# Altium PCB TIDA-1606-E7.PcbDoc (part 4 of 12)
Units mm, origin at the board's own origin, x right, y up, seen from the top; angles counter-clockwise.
Board outline 270 x 345 mm, 4 copper layers (Top Layer, Signal Layer 1, Signal Layer 2, Bottom Layer), stack 2.326 mm thick; 1282 components, 576 nets, 3628 pads, 4132 vias.
Unrouted connection lines stored in the file: 1719.
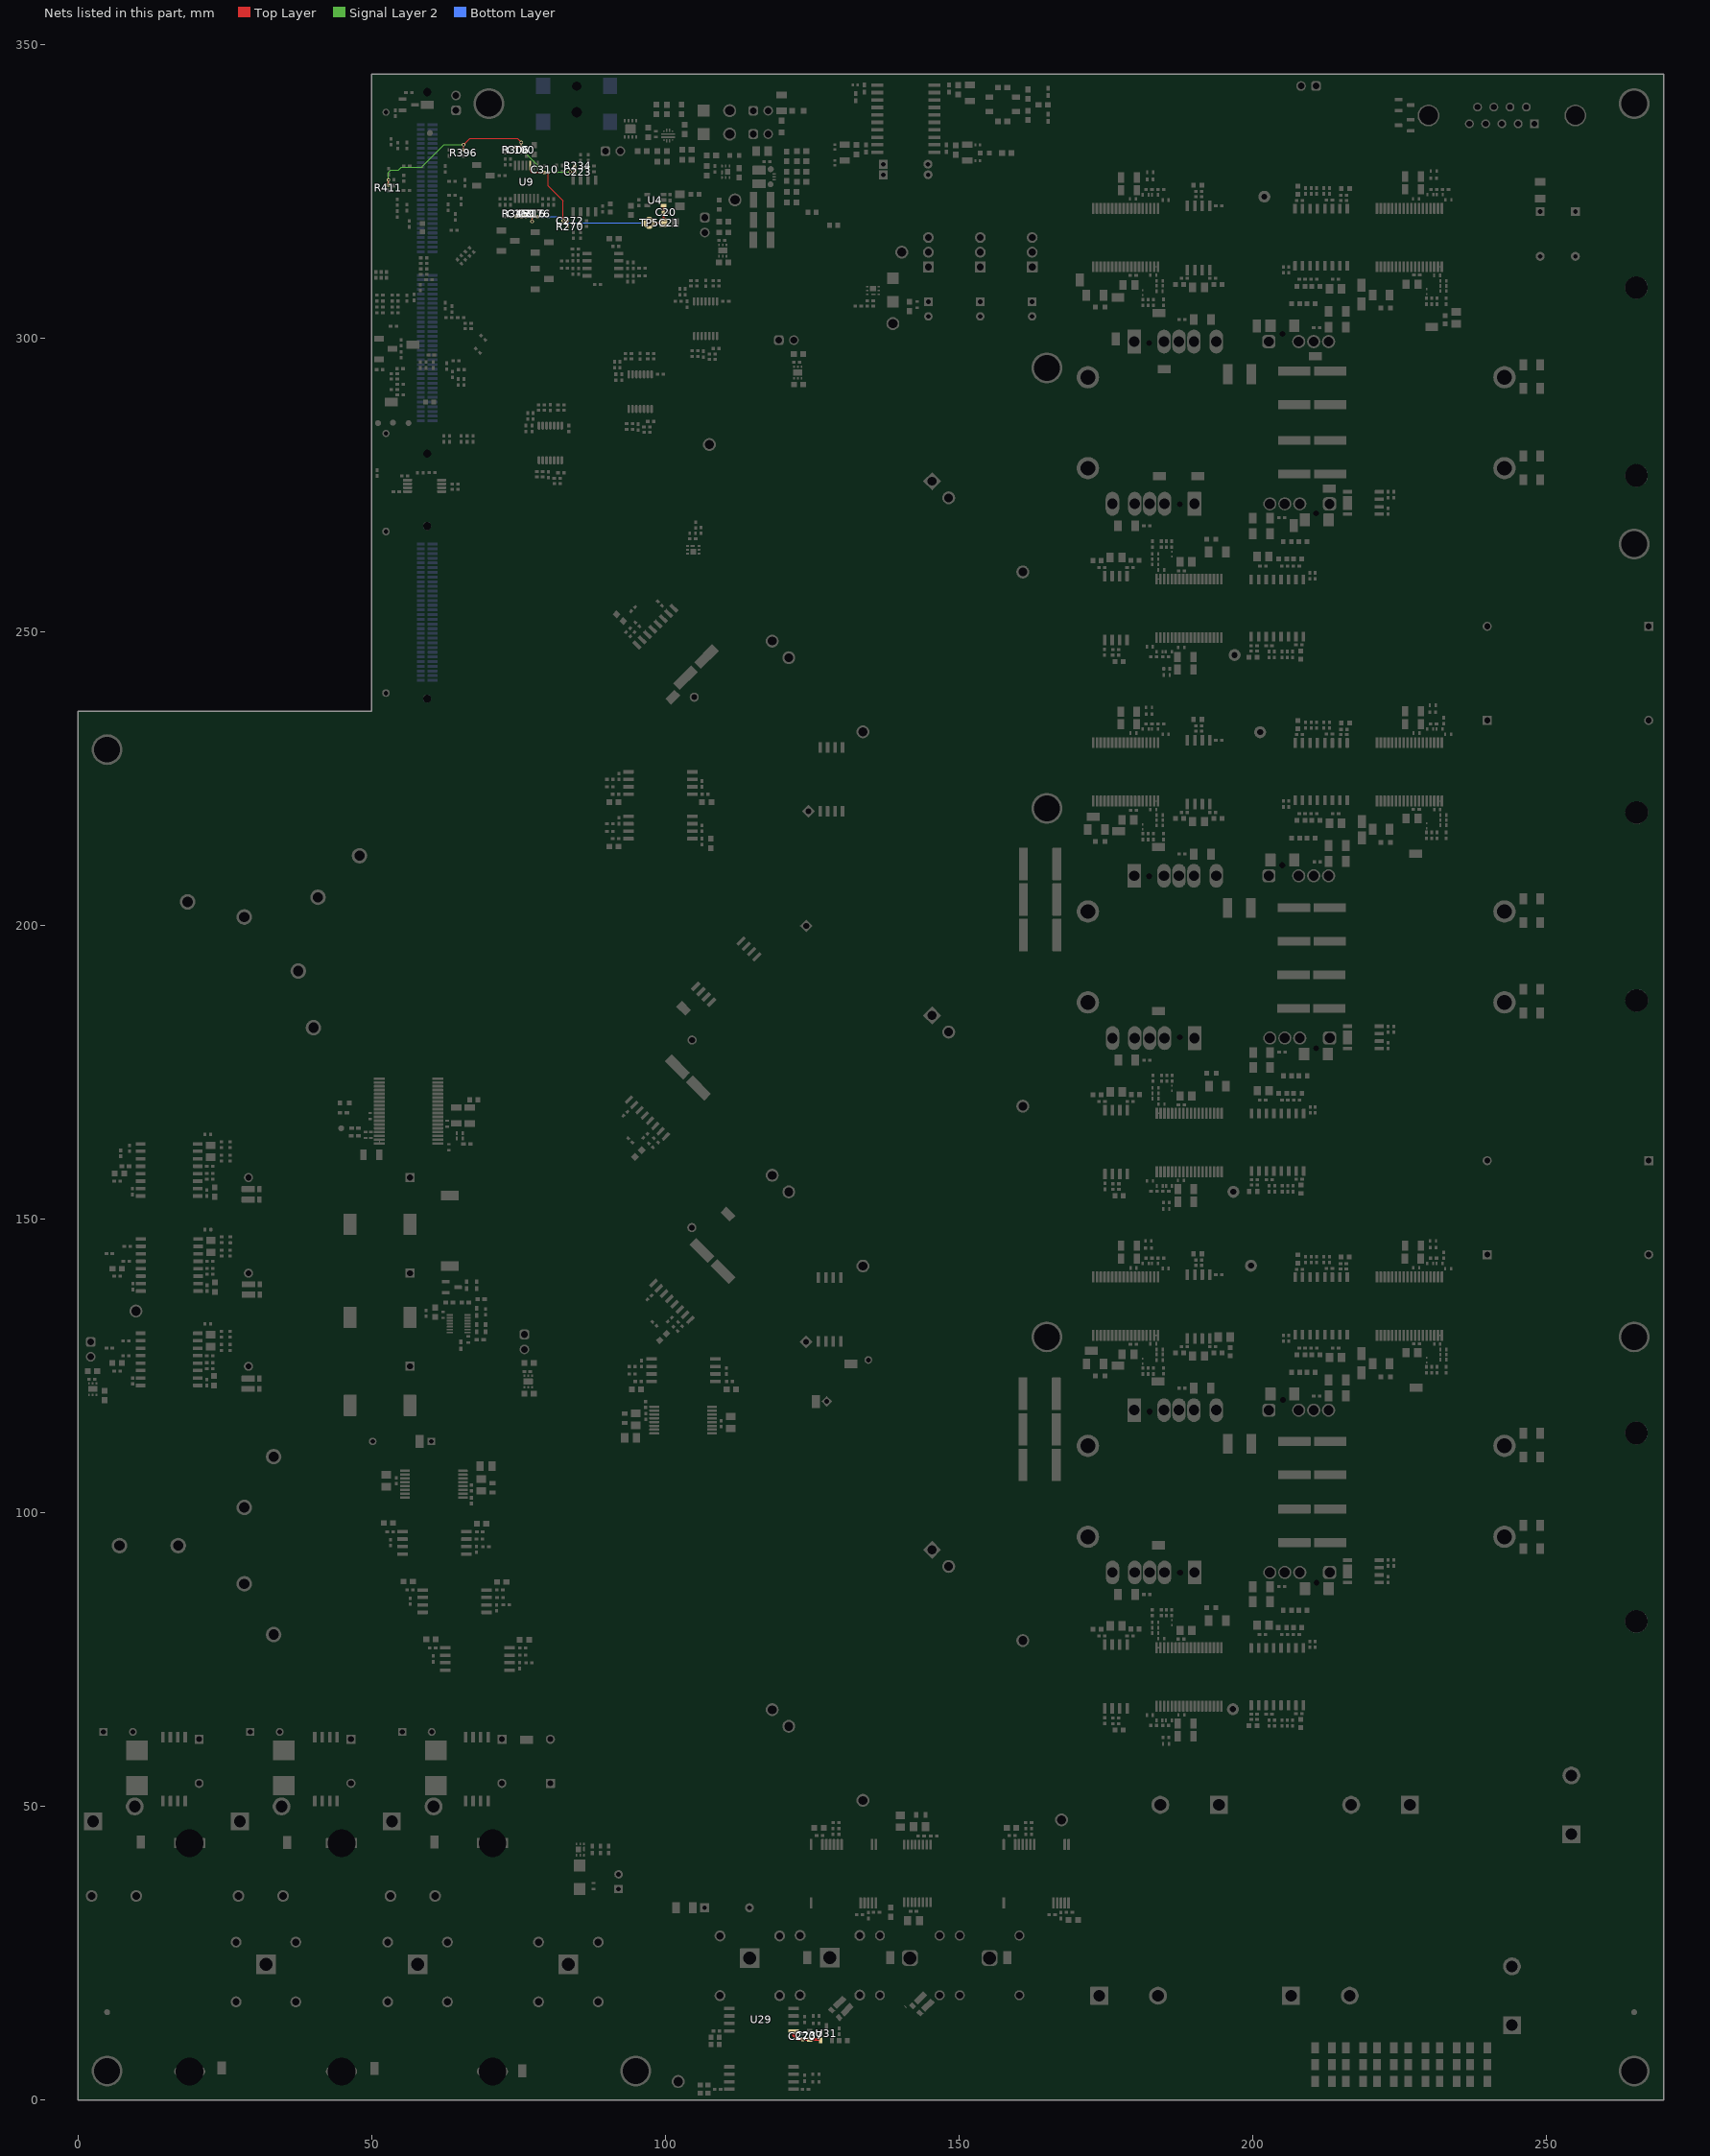
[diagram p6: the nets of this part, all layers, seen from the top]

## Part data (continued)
C17 C19 C22 C24 C25 C27 C28 C31 C34 C56 C59 C63 C66 C105 C110 C114 C119 C123 C128 C149 C165 C168 C176 C181 C189 C198 C202 C215 C221 C229 C237 C242 C252 C259 C266 C268 C269 C284 C293 C305 C309 C311 C323 C336 C352 C353 C356 C401 C409 C451 C452 C456 C484: library part CMP-0007121-4, "CAP, CERM, 2.2 uF, 16 V, +/- 10%, X7R, 0603", Cap_Case=0603, Manufacturer="Taiyo Yuden", Supplier Part Number 1=EMK107BB7225KA-T-ND, TempCo=X7R, Tolerance_%=10%, Value1=Unknown, Value2=16V, ValueDisplayed=2.2uF
C32 C60 C175 C197 C223 C230 C231 C272 C275 C297 C324 C357 C444 C455: library part CMP-0006309-2, "CAP, CERM, 1000 pF, 50 V, +/- 5%, C0G/NP0, AEC-Q200 Grade 1, 0402", Cap_Case=0402, Manufacturer=TDK, Supplier Part Number 1=445-6885-1-ND, TempCo=C0G/NP0, Tolerance_%=5%, Value1=Unknown, Value2=50V, ValueDisplayed=1000pF
C33 C342: library part CMP-0006412-2, "CAP, CERM, 1000 pF, 50 V, +/- 5%, C0G/NP0, 0402", Cap_Case=0402, Manufacturer=MuRata, Supplier Part Number 1=490-3244-1-ND, TempCo=C0G/NP0, Tolerance_%=5%, Value1=Unknown, Value2=50V, ValueDisplayed=1000pF
C35 C106 C111 C112 C115 C120 C121 C124 C129 C130 C454: library part CMP-0006673-2, "CAP, CERM, 1000 pF, 50 V, +/- 10%, X7R, 0402", Cap_Case=0402, Manufacturer=MuRata, Supplier Part Number 1=490-1303-1-ND, TempCo=X7R, Tolerance_%=10%, Value1=Unknown, Value2=50V, ValueDisplayed=1000pF
C36 C41 C46 C51 C395 C396: library part CMP-0097092-1, "240 µF 500 V Aluminum Electrolytic Capacitors Radial, Can - Snap-In 859.2mOhm @ 100Hz 7000 Hrs @ 105°C", Digikey Part Number=ALA8DA241CD500-ND, Leakage Current=360uA, Manufacturer=KEMET, Mouser Part Number=80-ALA8DA241CD500, Operating Temperature Range="-40°C to +105°C", Tolerance_%=20%, ValueDisplayed=240uF
C37 C42 C47 C52: library part CMP-0121428-1, "3.9 µF Film Capacitor 700V Polypropylene (PP), Metallized Radial", Digikey Part Number=495-B32774H8395K000-ND, Manufacturer=TDK, Mouser Part Number=871-B32774H8395K000, Operating Temperature Range="-40°C to +105°C", Tolerance_%=10%, ValueDisplayed=3.9uF
C38 C39 C40 C43 C44 C45 C48 C49 C50 C53 C54 C55 C67 C71 C72 C73 C75 C76: library part CMP-0098327-1, "0.25 µF ±20% 500V Ceramic Capacitor 2220 (5750 Metric)", Digikey Part Number=495-B58043E5254M052CT-ND, Manufacturer=TDK, Mouser Part Number=871-B58043E5254M052, Operating Temperature Range="-40°C to +150°C", Tolerance_%=20%, ValueDisplayed=250nF
C61 C102 C146 C154 C156 C162 C186 C194 C196 C199 C207 C209 C212 C225 C228 C240 C249 C256 C263 C290 C298 C300 C301 C306 C326 C333 C341 C343 C348 C349 C358 C386 C387 C388 C389 C390 C391 C392 C461 C462 C463 C464 C465 C466 C467 C468 C470 C471 C472 C473 C474 C475 C476 C477 C478 C479 C480 C481: library part CMP-0006410-2, "CAP, CERM, 100 pF, 50 V, +/- 5%, C0G/NP0, 0402", Cap_Case=0402, Manufacturer=MuRata, Supplier Part Number 1=81-GRM1555C1H101JA1D, TempCo=C0G/NP0, Tolerance_%=5%, Value1=Unknown, Value2=50V, ValueDisplayed=100pF
C68 C69 C70 C77 C78 C79: library part CMP-0098409-1, "4.7 µF Film Capacitor 310V 630V Polypropylene (PP), Metallized Radial", Digikey Part Number=399-R523R447050P1M-ND, Manufacturer=KEMET, Mouser Part Number=80-R523R447050P1M, Operating Temperature Range="-40°C to +110°C", Tolerance_%=20%, ValueDisplayed=4.7uF, Voltage Ac Rating X=310V
C74 C80: library part CMP-0098408-1, "Cap Film 0.0047uF 1500V PP 10% Dipped 10mm 125°C Bulk", Digikey Part Number=399-R413F147050T1K-ND, Manufacturer=KEMET, Mouser Part Number=80-R413F147050T1K, Operating Temperature Range="-40°C to +125°C", Tolerance_%=10%, ValueDisplayed=4700pF, Voltage Ac Rating Y=300V
C81 C82 C83: library part CMP-0122968-1, "680pF ±10% 300VAC Ceramic Capacitor B Nonstandard SMD", Digikey Part Number=490-16261-1-ND, Manufacturer=Murata, Mouser Part Number=81-DK1B3EA681K86RBH1, Operating Temperature Range="-40°C to +125°C", TempCo=10%, Temperature Characteristic=B, ValueDisplayed=680pF, Voltage Ac Rating X=440V, Voltage Ac Rating Y=300V
C84: library part CMP-0122969-1, "4700 pF ±10% 305VAC Ceramic Capacitor U2J Nonstandard SMD", Digikey Part Number=490-EVA86Q7UTF472KA01KCT-ND, Manufacturer=Murata, Mouser Part Number=81-EVA86Q7UTF472KA1K, Operating Temperature Range="-55°C to +125°C", TempCo=-630/-1097ppm/°C, Temperature Characteristic=U2J, Tolerance_%=10%, ValueDisplayed=4700pF, Voltage Ac Rating X=305V
C85 C86 C90 C132 C133 C172 C173 C232 C233 C276 C277 C319 C320 C370 C376 C382 C397 C398 C405 C406 C413 C414 C421 C422 C441: library part CMP-0008802-2, "CAP, CERM, 10 uF, 50 V, +/- 10%, X7R, 1206", Cap_Case=1206, Manufacturer=Samsung, Supplier Part Number 1=1276-6767-1-ND, TempCo=X7R, Tolerance_%=10%, Value1=Unknown, Value2=50V, ValueDisplayed=10uF
C91: library part CMP-0006684-2, "CAP, CERM, 0.022 uF, 50 V, +/- 10%, X7R, 0402", Cap_Case=0402, Manufacturer=MuRata, Supplier Part Number 1=490-3884-1-ND, TempCo=X7R, Tolerance_%=10%, Value1=Unknown, Value2=50V, ValueDisplayed=0.022uF
C93 C144 C145 C184 C185 C244 C245 C288 C289 C331 C332 C403 C404 C411 C412 C419 C420 C427 C428: library part CMP-0006318-2, "CAP, CERM, 330 pF, 50 V, +/- 10%, X7R, AEC-Q200 Grade 1, 0402", Cap_Case=0402, Manufacturer=TDK, Supplier Part Number 1=445-6887-1-ND, TempCo=X7R, Tolerance_%=10%, Value1="6.53276 ohm", Value2=50V, ValueDisplayed=330pF
C97: library part CMP-0082113-1, "CAP, CERM, 1 µF, 25 V,+/- 20%, X7R, AEC-Q200 Grade 1, 0603", Cap_Case=0603, Manufacturer=TDK, Supplier Part Number 1=445-12548-2-ND, TempCo=X7R, Tolerance_%=20%, Value2=25V, ValueDisplayed=1µF
C99: library part CMP-0006307-2, "CAP, CERM, 10 pF, 50 V, +/- 5%, C0G/NP0, AEC-Q200 Grade 1, 0402", Cap_Case=0402, Manufacturer=TDK, Supplier Part Number 1=445-5584-1-ND, TempCo=C0G/NP0, Tolerance_%=5%, Value1=Unknown, Value2=50V, ValueDisplayed=10pF
C100 C167 C169 C313 C316 C335: library part CMP-0006403-2, "CAP, CERM, 750 pF, 25 V, +/- 5%, C0G/NP0, 0402", Cap_Case=0402, Manufacturer=MuRata, Supplier Part Number 1=GRM1555C1E751JA01D-ND, TempCo=C0G/NP0, Tolerance_%=5%, Value1=Unknown, Value2=25V, ValueDisplayed=750pF
C101: library part CMP-0006324-2, "CAP, CERM, 0.01 uF, 50 V, +/- 10%, X7R, AEC-Q200 Grade 1, 0402", Cap_Case=0402, Manufacturer=TDK, Supplier Part Number 1=445-6893-1-ND, TempCo=X7R, Tolerance_%=10%, Value1="0.333065 ohm", Value2=50V, ValueDisplayed=0.01uF
C113 C122 C131: library part CMP-0080742-1, "CAP, CERM, 0.033 µF, 50 V,+/- 5%, C0G/NP0, AEC-Q200 Grade 1, 0805", Cap_Case=0805, Manufacturer=TDK, Supplier Part Number 1=445-6950-1-ND, TempCo=C0G/NP0, Tolerance_%=5%, Value2=50V, ValueDisplayed=0.033µF
C135 C136 C137 C139 C142 C148 C161 C164 C179 C182 C188 C193 C201 C204 C214 C217 C239 C251 C258 C265 C280: library part CMP-0007885-2, "CAP, CERM, 4.7 uF, 35 V, +/- 10%, X7R, 0805", Cap_Case=0805, Manufacturer=TDK, Supplier Part Number 1=445-7555-1-ND, TempCo=X7R, Tolerance_%=10%, Value1="0.002346 ohm", Value2=35V, ValueDisplayed=4.7uF
C140 C141 C151 C153 C191 C206 C219 C236 C241 C248 C255 C262 C279: library part CMP-0007048-4, "CAP, CERM, 0.33 uF, 50 V, +/- 10%, X7R, 0603", Cap_Case=0603, Manufacturer=TDK, Supplier Part Number 1=445-5950-1-ND, TempCo=X7R, Tolerance_%=10%, Value1="0.016574 ohm", Value2=50V, ValueDisplayed=0.33uF
C224 C273: library part CMP-0006358-2, "CAP, CERM, 0.022 uF, 50 V, +/- 10%, C0G/NP0, 0402", Cap_Case=0402, Manufacturer=MuRata, Supplier Part Number 1=490-4763-1-ND, TempCo=C0G/NP0, Tolerance_%=10%, Value1=Unknown, Value2=50V, ValueDisplayed=0.022uF
C227 C274 C310 C329 C340 C344 C345 C485 C486 C487 C488 C489 C490 C492: library part CMP-0006376-2, "CAP, CERM, 300 pF, 25 V, +/- 5%, C0G/NP0, 0402", Cap_Case=0402, Manufacturer=MuRata, Supplier Part Number 1=GRM1555C1E301JA01D-ND, TempCo=C0G/NP0, Tolerance_%=5%, Value1=Unknown, Value2=25V, ValueDisplayed=300pF
C246 C253 C260: library part CMP-0006614-2, "CAP, CERM, 0.1 uF, 50 V, +/- 20%, X5R, 0402", Cap_Case=0402, Manufacturer=MuRata, Supplier Part Number 1=GRM155R61H104ME14D-ND, TempCo=X5R, Tolerance_%=20%, Value1=Unknown, Value2=50V, ValueDisplayed=0.1uF
C285 C295 C346 C360 C361 C364 C445 C446 C449: library part CMP-0008377-2, "CAP, CERM, 22 uF, 10 V, +/- 20%, X7R, 0805", Cap_Case=0805, Manufacturer=MuRata, Supplier Part Number 1=81-GRM21BZ71A226ME5L, TempCo=X7R, Tolerance_%=20%, Value1=Unknown, Value2=10V, ValueDisplayed=22uF
C286 C292 C362 C363 C447 C448: library part CMP-0006327-2, "CAP, CERM, 0.015 uF, 50 V, +/- 10%, X7R, AEC-Q200 Grade 1, 0402", Cap_Case=0402, Manufacturer=TDK, Supplier Part Number 1=445-6894-1-ND, TempCo=X7R, Tolerance_%=10%, Value1="0.2162 ohm", Value2=50V, ValueDisplayed=0.015uF
C365 C366 C367 C368: library part CMP-0010339-1, "CAP, AL, 100 uF, 25 V, +/- 20%, 0.13 ohm, TH", Cap_Case=6.3x11.2, Manufacturer=Panasonic, Supplier Part Number 1=P12924-ND, Tolerance_%=20%, Value1="0.13 ohm", Value2=25V, ValueDisplayed=100uF
C371 C375 C381: library part CMP-0079154-1, "CAP, CERM, 1 µF, 16 V,+/- 10%, X7R, AEC-Q200 Grade 1, 0603", Cap_Case=0603, Manufacturer=MuRata, Supplier Part Number 1=490-12657-1-ND, TempCo=X7R, Tolerance_%=10%, Value2=16V, ValueDisplayed=1µF
C372 C380: library part CMP-0006674-2, "CAP, CERM, 0.01 uF, 50 V, +/- 10%, X7R, 0402", Cap_Case=0402, Manufacturer=MuRata, Supplier Part Number 1=490-4516-1-ND, TempCo=X7R, Tolerance_%=10%, Value1=Unknown, Value2=50V, ValueDisplayed=0.01uF
C377 C379: library part CMP-0006251-2, "CAP, CERM, 68 pF, 50 V, +/- 5%, C0G/NP0, 0402", Cap_Case=0402, Manufacturer=TDK, Supplier Part Number 1=445-1245-1-ND, TempCo=C0G/NP0, Tolerance_%=5%, Value1=Unknown, Value2=50V, ValueDisplayed=68pF
C378: library part CMP-0006987-4, "CAP, CERM, 4700 pF, 50 V, +/- 10%, X7R, 0603", Cap_Case=0603, Manufacturer=Kemet, Supplier Part Number 1=399-5337-1-ND, TempCo=X7R, Tolerance_%=10%, Value1=Unknown, Value2=50V, ValueDisplayed=4700pF
C458 C459 C460: library part CMP-0009326-2, "CAP, CERM, 0.1 uF, 1000 V, +/- 10%, X7R, 1812", Cap_Case=1812, Manufacturer=Kemet, Supplier Part Number 1=399-6523-1-ND, TempCo=X7R, Tolerance_%=10%, Value1=Unknown, Value2=1000V, ValueDisplayed=0.1uF
D1 D3 D4 D18 D22 D23 D24 D28 D29 D30 D31 D32 D33: library part CMP-0002894-2, "LED, Green, SMD", Color=green, Manufacturer="Wurth Elektronik", Value1=W, Value2=2V
D2: library part CMP-0028350-2, "Diode, Schottky, 30 V, 3 A, SMA", Manufacturer="Diodes Inc.", Value1=3A, Value2=0.5V
D5 D6: library part CMP-0028389-2, "Diode, Schottky, 60 V, 1 A, SMA", Manufacturer="Diodes Inc.", Value1=1A, Value2=0.7V
D7 D14 D16 D19 D20 D21 D25 D26 D27: library part CMP-0077005-2, "Diode, Schottky, 30 V, 0.1 A, SOD-923", Manufacturer="ON Semiconductor", Value1=0.1A, Value2=0.525V
D8 D10 D11 D12 D15 D17: library part CMP-0095286-1, "Diode Standard 1200 V 1A Surface Mount DO-214AC (SMA)", Digikey Part Number=US1Q-TPMSCT-ND, Forward Current=1A, Manufacturer=MCC, Max Surge Forward Current=30A, Mouser Part Number=833-US1Q-TP, Operating Temperature Range="-55°C to +150°C", Peak Reverse Current=5uA, ValueDisplayed=45pF
F1 F2 F3: library part CMP-0097107-1, "Fuse Cartridge 20A 600V Cartridge 38 X 10.3 X 11.7mm", Digikey Part Number=118-PF-HT1-20-ND, Fuse Current=20A, Fuse Interrupt Dc Current=50000A, Manufacturer=Bourns, Mouser Part Number=652-PF-HT1-20, Operating Temperature Range="-55°C to +125°C"
FB1 FB2 FB3 FB4 FB5 FB6 FB7 FB8 FB9 FB10 FB11 FB12 FB13 FB14 FB15 FB21 FB22 FB23: library part CMP-0091663-1, "1.8 kOhms @ 100MHz 1 Power, Signal Line Ferrite Bead 0402 (1005 Metric) 210mA 2.1Ohm", Digikey Part Number=732-74269244182CT-ND, Impedance At Frequency="1800O @ 100MHz", Manufacturer="Wurth Electronics", Mouser Part Number=710-74269244182, Operating Temperature Range="-55°C to +125°C", Test Frequency=1GHz, Tolerance_%=25%
FB16 FB17 FB18 FB19 FB20: library part CMP-0041881-1, "Chip Ferrite Bead, 0402, 330O @ 100MHz, 0.205O, 25%, 1.1A", Impedance At Frequency="330O @ 100MHz", Manufacturer=Murata, Operating Temperature Range="-55°C to +125°C", Test Frequency=100MHz, Tolerance_%=25%
FB24 FB25: library part CMP-0124053-1, "Ferrite Bead 600Ohm 0.9A 0.17Ohm Wirewound 2-Pin 0603 Paper T/R", Digikey Part Number=587-LCMGA160808T601RGCT-ND, Impedance At Frequency="600O @ 100MHz", Manufacturer="Taiyo Yuden", Mouser Part Number=963-LCMGA160808T601R, Operating Temperature Range="-40°C to +125°C", Tolerance_%=25%
FID1 FID2 FID3: library part CMP-0077181-1, "Fiducial mark.  There is nothing to buy or mount.", Manufacturer=N/A
J1 J2 J8 J10 J11 J12 J25 J27 J31: library part CMP-0054794-2, "Header, 2.54 mm, 2x1, Gold, TH", Color=Black, Manufacturer="Wurth Elektronik", Supplier Part Number 1=732-5315-ND
J3: library part CMP-0075012-1, "Power Jack, SMT", Manufacturer="CUI Inc.", Supplier Part Number 1=CP-002AHPJDKR-ND
J4 J5 J6 J22 J23: library part CMP-0055045-1, "Shorting Jumper, 7.62mm, 2 Position, Gold, TH", Manufacturer=Mill-Max, Supplier Part Number 1=ED1334-ND
J13: library part CMP-0055799-1, "Panel Socket, 24A, R/A, Gold, TH", Color=Red, Current_A=24A, Manufacturer="Cliff Electronic Components", Supplier Part Number 1=20T2058, Voltage_V=1kV
J14 J16 J17: library part CMP-0098296-2, "Banana Test Connector, Socket, PCB Mount, 24 A, 1 kV, Gold Plated Contacts, Brown", Current_A=24A, Digikey Part Number=4654-FCR7350N-ND, Manufacturer="CLIFF Electronic Components", Operating Temperature Range="-40°C to +80°C", Voltage_V=1kV
J15: library part CMP-0032023-2, "Banana Jack Connector Standard Banana Solder Yellow", Current_A=24A, Digikey Part Number=4654-FCR7350Y-ND, Manufacturer="CLIFF Electronic Components", Operating Temperature Range="-40°C to +80°C", Voltage_V=1kV
J18: library part CMP-0055798-1, "Panel Socket, 24A, R/A, Gold, TH", Color=Black, Current_A=24A, Manufacturer="Cliff Electronic Components", Supplier Part Number 1=20T2055, Voltage_V=1kV
J19 J20 J21: library part CMP-0122568-1, "Mini-Latch™ Wire-to-Board Header, Vertical, with Friction Ramp, 3 Circuits, Gold (Au) Plating", Current_A=3A, Digikey Part Number=23-0022111031-ND, Manufacturer=Molex, Mouser Part Number=538-22-11-1031, Operating Temperature Range="-40°C to +105°C", Voltage_V=250V
J24: library part CMP-0054820-2, "Receptacle, D-Sub, 9 Position, R/A, TH", Color=Black, Current_A=3A, Manufacturer="Wurth Elektronik", Supplier Part Number 1=16T0655, Voltage_V=125V
J26: library part CMP-0085713-2, "Receptacle, 0.8mm, 60x2, Gold with Tin tail, SMT", Color=Black, Manufacturer=Samtec
J29: library part CMP-0092559-1, "60 Position Female Connector Non Specified - Dual Edge Gold 0.031\" (0.80mm) Black", Current_A=2.8A, Digikey Part Number=SAM12638-ND, Manufacturer=Samtec, Mouser Part Number=200-HSEC813001LRA, Operating Temperature Range="-55°C to +125°C", Voltage_V=240V
J30: library part CMP-0098294-2, "Banana Test Connector, Socket, PCB Mount, 24 A, 1 kV, Gold Plated Contacts, Green", Current_A=24A, Digikey Part Number=4654-FCR7350G-ND, Manufacturer="CLIFF Electronic Components", Operating Temperature Range="-40°C to +80°C", Voltage_V=1kV
K1 K2 K3: library part CMP-0042926-1, "General Purpose Relay SPST-NO (1 Form A) 12VDC Coil Through Hole", Coil Power_W=450mW, Coil Resistance=320O, Coil Voltage_VDC=12V, Contact Rating_A=16A, Digikey Part Number=41-OJS-SH-112HEF,00000-ND, Manufacturer="TE Connectivity", Mouser Part Number=655-2071556-3, Operating Temperature Range=to
L1 L2 L3: library part CMP-0122793-1, "PFC Inductor", Manufacturer=Bourns, Operating Temperature Range=to, Test Frequency=100kHz, Tolerance_%=10%
L4 L5: library part CMP-0098429-2, "Common Mode Choke", Manufacturer="Kaschke Components", Operating Temperature Range="-25°C to +125°C", Test Frequency=10kHz, Tolerance_%=30%
L6 L9: library part CMP-0003288-1, "Ferrite Bead, 1000 ohm @ 100 MHz, 1 A, 1206", Manufacturer="Wurth Elektronik", Supplier Part Number 1=732-6718-1-ND, Value1="0.3 ohm", Value2=1A, ValueDisplayed="1000 ohm"
L7 L8: library part CMP-0003155-2, "Ferrite Bead, 26 ohm @ 100 MHz, 6.5 A, 0603", Manufacturer="Wurth Elektronik", Supplier Part Number 1=732-6117-1-ND, Value1="0.005 ohm", Value2=6.5A, ValueDisplayed="26 ohm"
L11 L12 L14: library part CMP-0100992-1, "WE-PMI SMT Power Multilayer Inductor, size 0603, 2.2uH, 0.8A, 375mOhm", Case/Size Code=0603, DC Resistance=375mOhm, Inductance=2.2uH, Inductance Tolerance=20%, Manufacturer="Wurth Elektronik", Operating Temperature Max=125°C, Operating Temperature Min=-40°C, Rated Current=0.8A, Saturation Current=0.28A, Self Resonant Frequency=80MHz
L13: library part CMP-0084086-1, "100µH @ 100kHz 2 Line Common Mode Choke Surface Mount 5.8 kOhms @ 10MHz 150mA DCR 2Ohm", Digikey Part Number=445-3959-1-ND, Impedance At Frequency="5800O @ 10MHz", Manufacturer=TDK, Mouser Part Number=810-ACT45B1012PTL003, Operating Temperature Range="-40°C to +150°C", Test Frequency=100kHz, Tolerance_%=+50/-30%
LBL1: library part CMP-0003625-1, "Thermal Transfer Printable Labels, 0.650\" W x 0.200\" H - 10,000 per roll", Manufacturer=Brady, Supplier Part Number 1=97C5133
Logo1: library part CMP-0074844-2, Manufacturer="Texas Instruments"
LOGO2 LOGO6 LOGO9 LOGO10 LOGO11: library part CMP-0074837-2, "IEC 61010-1 Hot Surface Warning", Manufacturer="Texas Instruments"
Logo3: library part CMP-0074847-1, "FCC_disclaimer"
Logo4: library part CMP-0074769-4, Manufacturer="Texas Instruments"
LOGO5 LOGO7 LOGO8 LOGO12 LOGO13: library part CMP-0074835-1, "IEC 61010-1 High Voltage Warning"
MP1 MP2 MP3 MP4 MP5 MP6: library part CMP-0121069-1, "Heatsink; TO-247; 75 x 20.47 x 38mm; Spring Clip Mount", Digikey Part Number=C247-075-3AE-ND, Manufacturer=Ohmite, Mating Package=TO-247, Mouser Part Number=588-C247-075-3AE, Operating Temperature Range=to
MP7 MP8 MP9 MP10 MP11 MP12 MP13 MP14 MP15 MP16 MP17: library part CMP-0121346-1, Digikey Part Number=732-7092-1-ND, Manufacturer="Würth Elektronik", Mouser Part Number=710-9774040960R, Operating Temperature Range="-55°C to +150°C"
MP18 MP19 MP20 MP21 MP22 MP23: library part CMP-0122371-1, Digikey Part Number=36-613-ND, Manufacturer=Keystone, Mouser Part Number=534-613, Operating Temperature Range=to
MP24 MP25 MP26: library part CMP-0122386-3, "DC FAN", Manufacturer=Wakefield-Vette, Operating Temperature Range="-10°C to +70°C"
NT9 NT17 NT18 NT19 NT20 NT21 NT22 NT23 NT24 NT25 NT26: library part CMP-0078142-6, "Single point connection between nets.", Manufacturer=N/A
Q1 Q14 Q15: library part CMP-0000585-1, "MOSFET, N-CH, 30 V, 22 A, DQK0006C (WSON-6)", Alternate Manufacturer=None, Manufacturer="Texas Instruments", Supplier Part Number 1=296-37193-1-ND, Value1=0.02, Value2="2.4 nC"
Q2 Q3 Q4 Q11 Q12 Q13: library part CMP-0085490-1, "MOSFET, N-CH, 1200 V, 30 A, TO-247-4", Alternate Manufacturer=None, Manufacturer=Cree, Value1="? ohm", Value2="51 nC"
Q5 Q6 Q7 Q8 Q9 Q10: library part CMP-0096829-1, "Silicon Carbide Power MOSFET N-Channel 650 V 37A (Tc) 150W (Tc) Through Hole TO-247-4L", Digikey Part Number=1697-C3M0060065K-ND, Drain To Source Breakdown Voltage=650V, Input Capacitace At Vds="1020pF @ 600V", Manufacturer=Wolfspeed, Mouser Part Number=941-C3M0060065K, Operating Temperature Range="-40°C to +175°C", Power_W=150W, Pulse Drain Current=99A, Typ Forward Diode Voltage=5.1V
Q16: library part CMP-0076725-1, "30-V N-Channel NexFET™ Power MOSFET", Manufacturer="Texas Instruments"
R1: library part CMP-0023128-4, "RES, 470 k, 1%, 0.1 W, 0603", Manufacturer=Yageo, Power_W=100mW, Supplier Part Number 1=311-470KHRCT-ND, TempCo="100 ppm/C", Tolerance_%=1%, Value2=0.1W, Value_Code=470k
R2 R6 R8 R18: library part CMP-0023133-5, "RES, 47.0 k, 1%, 0.1 W, 0603", Manufacturer=Yageo, Power_W=100mW, Supplier Part Number 1=311-47.0KHRCT-ND, TempCo="100 ppm/C", Tolerance_%=1%, Value2=0.1W, Value_Code=47k0, ValueDisplayed=47.0k
R3: library part CMP-0022870-5, "RES, 1.10 k, 1%, 0.1 W, 0603", Manufacturer=Yageo, Power_W=100mW, Supplier Part Number 1=311-1.10KHRCT-ND, TempCo="100 ppm/C", Tolerance_%=1%, Value2=0.1W, Value_Code=1k10, ValueDisplayed=1.10k
R4: library part CMP-0023203-5, "RES, 5.60 k, 1%, 0.1 W, 0603", Manufacturer=Yageo, Power_W=100mW, Supplier Part Number 1=311-5.60KHRCT-ND, TempCo="100 ppm/C", Tolerance_%=1%, Value2=0.1W, Value_Code=5k60, ValueDisplayed=5.60k
R5 R166 R205 R220 R236 R296 R335: library part CMP-0022763-5, "RES, 11.0 k, 1%, 0.1 W, 0603", Manufacturer=Yageo, Power_W=100mW, Supplier Part Number 1=311-11.0KHRCT-ND, TempCo="100 ppm/C", Tolerance_%=1%, Value2=0.1W, Value_Code=11k0, ValueDisplayed=11.0k
R7: library part CMP-0023000-5, "RES, 2.00 k, 1%, 0.1 W, 0603", Manufacturer=Yageo, Power_W=100mW, Supplier Part Number 1=311-2.00KHRCT-ND, TempCo="100 ppm/C", Tolerance_%=1%, Value2=0.1W, Value_Code=2k00, ValueDisplayed=2.00k
R9: library part CMP-0022816-5, "RES, 15.0 k, 1%, 0.1 W, 0603", Manufacturer=Yageo, Power_W=100mW, Supplier Part Number 1=311-15.0KHRCT-ND, TempCo="100 ppm/C", Tolerance_%=1%, Value2=0.1W, Value_Code=15k0, ValueDisplayed=15.0k
R10 R62 R66 R133 R135 R138 R326 R343 R354 R355 R356 R357 R358 R360 R362 R365 R366 R367: library part CMP-0026703-1, "RES, 49.9, 1%, 0.1 W, AEC-Q200 Grade 0, 0402", Manufacturer=Panasonic, Power_W=100mW, Supplier Part Number 1=P49.9LCT-ND, TempCo="100 ppm/C", Tolerance_%=1%, Value2=0.1W, Value_Code=49R9, ValueDisplayed=49.9
R11: library part CMP-0023180-5, "RES, 54.9 k, 1%, 0.1 W, 0603", Manufacturer=Yageo, Power_W=100mW, Supplier Part Number 1=311-54.9KHRCT-ND, TempCo="100 ppm/C", Tolerance_%=1%, Value2=0.1W, Value_Code=54k9, ValueDisplayed=54.9k
R12: library part CMP-0022917-4, "RES, 220 k, 1%, 0.1 W, 0603", Manufacturer=Yageo, Power_W=100mW, Supplier Part Number 1=311-220KHRCT-ND, TempCo="100 ppm/C", Tolerance_%=1%, Value2=0.1W, Value_Code=220k
R13 R16: library part CMP-0023020-5, "RES, 30.0 k, 1%, 0.1 W, 0603", Manufacturer=Yageo, Power_W=100mW, Supplier Part Number 1=311-30.0KHRCT-ND, TempCo="100 ppm/C", Tolerance_%=1%, Value2=0.1W, Value_Code=30k0, ValueDisplayed=30.0k
R14: library part CMP-0023404-3, "RES, 10.0 k, 0.1%, 0.1 W, 0603", Manufacturer="Susumu Co Ltd", Power_W=100mW, Supplier Part Number 1=RG16P10.0KBCT-ND, TempCo="25 ppm/C", Tolerance_%=0.1%, Value2=0.1W, Value_Code=10k0, ValueDisplayed=10.0k
R15 R382: library part CMP-0082532-1, "RES, 499, 1%, 0.1 W, 0603", Manufacturer=Vishay-Dale, Power_W=100mW, Supplier Part Number 1=541-3986-1-ND, TempCo="100 ppm/C", Tolerance_%=1%, Value2=0.1W, Value_Code=499R, ValueDisplayed=499
R17 R162 R201 R216 R231 R292 R331: library part CMP-0025885-5, "RES, 0, 5%, 0.1 W, 0603", Manufacturer=Yageo, Power_W=100mW, Supplier Part Number 1=311-0.0GRCT-ND, TempCo="200 ppm/C", Tolerance_%=5%, Value2=0.1W, Value_Code=0000, ValueDisplayed=0
R19 R28 R29 R37: library part CMP-0065359-1, "RES, 15.0 k, .1%, .063 W, AEC-Q200 Grade 0, 0402", Manufacturer=Panasonic, Power_W=63mW, Supplier Part Number 1=P15KDCCT-ND, TempCo="25 ppm/C", Tolerance_%=0.1%, Value1=.1%, Value2=.063W, Value_Code=15k0, ValueDisplayed=15.0k
R20 R26 R27 R30 R63 R65 R68 R70 R73 R75 R167 R171 R206 R207 R221 R222 R225 R237 R251 R297 R300 R336: library part CMP-0026656-1, "RES, 100, 1%, 0.1 W, 0402", Manufacturer=Panasonic, Power_W=100mW, Supplier Part Number 1=P100LCT-ND, TempCo="100 ppm/C", Tolerance_%=1%, Value2=0.1W, Value_Code=100R, ValueDisplayed=100
R21 R31 R71 R140 R143 R145 R304 R351 R353 R359 R361 R363 R364 R396 R411 R435 R437 R445 R446 R447 R448 R449 R450 R452 R457 R458 R459 R460 R462 R463 R464 R465 R466 R467 R469 R470 R471 R472 R475 R476 R477 R478 R481: library part CMP-0027004-2, "RES, 0, 5%, 0.063 W, 0402", Manufacturer="Yageo America", Power_W=63mW, Supplier Part Number 1=311-0.0JRCT-ND, TempCo="200 ppm/C", Tolerance_%=5%, Value2=0.063W, Value_Code=0000, ValueDisplayed=0
R22 R25 R32 R34 R40 R111 R152 R155 R176 R179 R181 R184 R193 R194 R239 R241 R255 R256 R272 R274 R282 R285 R306 R309 R311 R313 R321 R324 R342 R345 R346 R348 R349 R505 R512 R513 R532 R533 R540 R541: library part CMP-0077124-1, "RES, 10.0 k, 0.1%, 0.1 W, AEC-Q200 Grade 0, 0402", Manufacturer=Vishay/Beyschlag, Power_W=100mW, Supplier Part Number 1=MCS0402-10.0K-MBCT-ND, TempCo="25 ppm/C", Tolerance_%=0.1%, Value2=0.1W, Value_Code=10k0, ValueDisplayed=10.0k
R23 R76 R109 R151 R153 R188 R191 R247 R250 R253 R259 R279 R280 R302 R316 R320 R509 R511 R529 R531 R537 R539: library part CMP-0078244-2, "RES, 30.0 k, 1%, 0.063 W, AEC-Q200 Grade 0, 0402", Manufacturer=Vishay-Dale, Power_W=63mW, Supplier Part Number 1=541-30.0KLCT-ND, TempCo="100 ppm/C", Tolerance_%=1%, Value2=0.063W, Value_Code=30k0, ValueDisplayed=30.0k
R24 R33 R180 R240 R273 R310 R347: library part CMP-0026283-2, "RES, 309, 1%, 0.063 W, AEC-Q200 Grade 0, 0402", Manufacturer=Vishay-Dale, Power_W=63mW, Supplier Part Number 1=541-309LCT-ND, TempCo="100 ppm/C", Tolerance_%=1%, Value2=0.063W, Value_Code=309R, ValueDisplayed=309
R35 R36 R157 R174 R196 R210 R211 R224 R226 R242 R246 R260 R264 R268 R384 R387: library part CMP-0081973-1, "RES, 0, 0%, 0.25 W, AEC-Q200 Grade 0, 0603", Manufacturer=Vishay-Dale, Power_W=250mW, Supplier Part Number 1=541-2779-1-ND, Tolerance_%=0%, Value2=0.25W, Value_Code=0
R38: library part CMP-0078193-1, "RES, 1.0 k, 5%, 0.1 W, AEC-Q200 Grade 0, 0402", Manufacturer=Panasonic, Power_W=100mW, Supplier Part Number 1=P1.0KJCT-ND, TempCo="200 ppm/C", Tolerance_%=5%, Value2=0.1W, Value_Code=1k00, ValueDisplayed=1.0k
R39: library part CMP-0026323-2, "RES, 38.3 k, 1%, 0.063 W, AEC-Q200 Grade 0, 0402", Manufacturer=Vishay-Dale, Power_W=63mW, Supplier Part Number 1=541-38.3KLCT-ND, TempCo="100 ppm/C", Tolerance_%=1%, Value2=0.063W, Value_Code=38k3, ValueDisplayed=38.3k
R41 R42 R43 R44 R45 R46 R47 R48 R49 R51 R52 R53 R54 R55 R56 R57 R58 R59: library part CMP-0018695-3, "RES, 510 k, 5%, 0.25 W, AEC-Q200 Grade 0, 1206", Manufacturer=Vishay-Dale, Power_W=250mW, Supplier Part Number 1=541-510KECT-ND, TempCo="200 ppm/C", Tolerance_%=5%, Value2=0.25W, Value_Code=510k
R50 R60 R77 R78 R79: library part CMP-0120177-1, "2 mOhms ±1% 1W Chip Resistor Wide 1206 (3216 Metric), 0612 Anti-Sulfur, Automotive AEC-Q200, Current Sense, Moisture Resistant, Pulse Withstanding Metal Element", Digikey Part Number=541-WSKW06122L000FEACT-ND, Manufacturer=Vishay, Mouser Part Number=71-WSKW06122L000FEA, Operating Temperature Range="-65°C to +170°C", Power_W=1W, TempCo=150ppm/°C, Tolerance_%=1%
R61: library part CMP-0026676-1, "RES, 2.00 k, 1%, 0.1 W, AEC-Q200 Grade 0, 0402", Manufacturer=Panasonic, Power_W=100mW, Supplier Part Number 1=P2.00KLCT-ND, TempCo="100 ppm/C", Tolerance_%=1%, Value2=0.1W, Value_Code=2k00, ValueDisplayed=2.00k
R64: library part CMP-0026708-1, "RES, 698, 1%, 0.1 W, 0402", Manufacturer=Panasonic, Power_W=100mW, Supplier Part Number 1=P698LCT-ND, TempCo="100 ppm/C", Tolerance_%=1%, Value2=0.1W, Value_Code=698R, ValueDisplayed=698
R67 R113 R130 R455: library part CMP-0026874-3, "RES, 200, 5%, 0.063 W, AEC-Q200 Grade 0, 0402", Manufacturer=Vishay-Dale, Power_W=63mW, Supplier Part Number 1=541-200JCT-ND, TempCo="200 ppm/C", Tolerance_%=5%, Value2=0.063W, Value_Code=200R, ValueDisplayed=200
R69: library part CMP-0026657-1, "RES, 1.00 k, 1%, 0.1 W, 0402", Manufacturer=Panasonic, Power_W=100mW, Supplier Part Number 1=P1.00KLCT-ND, TempCo="100 ppm/C", Tolerance_%=1%, Value2=0.1W, Value_Code=1k00, ValueDisplayed=1.00k
R72: library part CMP-0026668-1, "RES, 1.50 k, 1%, 0.1 W, AEC-Q200 Grade 0, 0402", Manufacturer=Panasonic, Power_W=100mW, Supplier Part Number 1=P1.50KLCT-ND, TempCo="100 ppm/C", Tolerance_%=1%, Value2=0.1W, Value_Code=1k50, ValueDisplayed=1.50k
R74 R80 R81 R82 R83 R84 R85 R86 R87 R88 R93 R99 R115 R129 R131 R158 R159 R160 R161 R175 R177 R178 R182 R185 R197 R198 R199 R200 R212 R213 R214 R215 R227 R228 R229 R230 R261 R265 R269 R288 R289 R290 R291 R301 R305 R307 R308 R314 R315 R327 R328 R329 R330 R337 R339 R340 R344 R350 R375 R376 R377 R378 R379 R381 R383 R389 R392 R398 R403 R413 R414 R415 R422 R424 R433 R436 R438 R439 R440 R441 R442 R443 R444: library part CMP-0025958-3, "RES, 10.0 k, 1%, 0.063 W, AEC-Q200 Grade 0, 0402", Manufacturer=Vishay-Dale, Power_W=63mW, Supplier Part Number 1=541-10.0KLCT-ND, TempCo="100 ppm/C", Tolerance_%=1%, Value2=0.063W, Value_Code=10k0, ValueDisplayed=10.0k
R89 R91 R94: library part CMP-0097004-1, "PTCEL Series 500 V 60 Ohm ±30 % Radial Inrush Current Limiter PTC Thermistor", Digikey Part Number=BC3317-ND, Hold Current=120mA, Manufacturer="Vishay Bccomponents", Mouser Part Number=594-PTCEL13R600LBE, Operating Temperature Range="-40°C to +105°C", Tolerance_%=30%
R90 R92 R95: library part CMP-0122581-1, "4.7 Ohms ±5% 3W Chip Resistor 2512 (6432 Metric) Automotive AEC-Q200 Thick Film", Digikey Part Number=4713-UPR25J4R7CT-ND, Manufacturer="Cal-Chip Electronics", Operating Temperature Range="-55°C to +155°C", Power_W=3W, TempCo=200ppm/°C, Tolerance_%=5%
R96 R97 R98 R100: library part CMP-0096768-1, "5 kA Varistor 1 Circuit Through Hole Disc 17mm", Clamping Voltage=730V, Digikey Part Number=118-ISOM5-275-B-L2-ND, Manufacturer=Bourns, Mouser Part Number=652-ISOM5-275-B-L2, Operating Temperature Range="-40°C to +125°C", ValueDisplayed=40pF
R101 R102 R103 R105 R106 R107 R108 R110 R112 R114 R116 R168: library part CMP-0026696-1, "RES, 33.0, 1%, 0.1 W, 0402", Manufacturer=Panasonic, Power_W=100mW, Supplier Part Number 1=P33.0LCT-ND, TempCo="100 ppm/C", Tolerance_%=1%, Value2=0.1W, Value_Code=33R0, ValueDisplayed=33.0
R104 R148 R187 R249 R267 R278 R299 R317 R434 R508 R528 R536: library part CMP-0026995-2, "RES, 100 k, 5%, 0.1 W, AEC-Q200 Grade 0, 0402", Manufacturer=Panasonic, Power_W=100mW, Supplier Part Number 1=P100KJCT-ND, TempCo="200 ppm/C", Tolerance_%=5%, Value2=0.1W, Value_Code=100k
R117 R118 R119 R120 R121 R122 R123 R124 R125 R126 R127 R128: library part CMP-0018180-2, "RES, 2.70, 1%, 0.25 W, 1206", Manufacturer="Yageo America", Power_W=250mW, Supplier Part Number 1=311-2.70FRCT-ND, TempCo="200 ppm/C", Tolerance_%=1%, Value2=0.25W, Value_Code=2R70, ValueDisplayed=2.70
R132 R137 R142: library part CMP-0026737-1, "RES, 47.0 k, 1%, 0.0625 W, 0402", Manufacturer="Yageo America", Power_W=62.5mW, Supplier Part Number 1=311-47.0KLRCT-ND, TempCo="100 ppm/C", Tolerance_%=1%, Value2=0.0625W, Value_Code=47k0, ValueDisplayed=47.0k
R134 R136 R139 R141 R144 R146 R238 R243 R271 R275 R287: library part CMP-0026765-1, "RES, 10.0, 0.1%, 0.063 W, 0402", Manufacturer="TE Connectivity", Power_W=63mW, Supplier Part Number 1=A102583CT-ND, TempCo="25 ppm/C", Tolerance_%=0.1%, Value2=0.063W, Value_Code=10R0, ValueDisplayed=10.0
R147 R154 R169 R208 R223 R245 R248 R263 R283 R298 R338 R527 R555 R556 R566: library part CMP-0026227-2, "RES, 2.00 k, 1%, 0.063 W, AEC-Q200 Grade 0, 0402", Manufacturer=Vishay-Dale, Power_W=63mW, Supplier Part Number 1=541-2.00KLCT-ND, TempCo="100 ppm/C", Tolerance_%=1%, Value2=0.063W, Value_Code=2k00, ValueDisplayed=2.00k
R149 R277 R284 R507 R565 R567: library part CMP-0026326-2, "RES, 392, 1%, 0.063 W, AEC-Q200 Grade 0, 0402", Manufacturer=Vishay-Dale, Power_W=63mW, Supplier Part Number 1=541-392LCT-ND, TempCo="100 ppm/C", Tolerance_%=1%, Value2=0.063W, Value_Code=392R, ValueDisplayed=392
R150 R173 R190 R252 R281 R319 R510 R530 R538: library part CMP-0026502-2, "RES, 66.5 k, 1%, 0.063 W, AEC-Q200 Grade 0, 0402", Manufacturer=Vishay-Dale, Power_W=63mW, Supplier Part Number 1=541-66.5KLCT-ND, TempCo="100 ppm/C", Tolerance_%=1%, Value2=0.063W, Value_Code=66k5, ValueDisplayed=66.5k
R156 R195 R257 R286 R325 R506 R514 R534 R542: library part CMP-0026795-1, "RES, 49.9 k, 0.1%, 0.063 W, 0402", Manufacturer="TT Electronics/IRC", Power_W=63mW, TempCo="25 ppm/C", Tolerance_%=0.1%, Value2=0.063W, Value_Code=49k9, ValueDisplayed=49.9k
R163 R202 R217 R232 R293 R332: library part CMP-0022687-3, "RES, 14.7 k, 1%, 0.1 W, AEC-Q200 Grade 0, 0603", Manufacturer=Panasonic, Power_W=100mW, Supplier Part Number 1=P14.7KHCT-ND, TempCo="100 ppm/C", Tolerance_%=1%, Value2=0.1W, Value_Code=14k7, ValueDisplayed=14.7k
R164 R165 R203 R204 R218 R219 R233 R235 R294 R295 R333 R334: library part CMP-0018573-3, "RES, 0, 5%, 0.25 W, AEC-Q200 Grade 0, 1206", Manufacturer=Vishay-Dale, Power_W=250mW, Supplier Part Number 1=541-0.0ECT-ND, TempCo="200 ppm/C", Tolerance_%=5%, Value2=0.25W, Value_Code=0000, ValueDisplayed=0
R170 R192 R209: library part CMP-0026164-2, "RES, 20.0, 1%, 0.063 W, AEC-Q200 Grade 0, 0402", Manufacturer=Vishay-Dale, Power_W=63mW, Supplier Part Number 1=541-20.0LCT-ND, TempCo="100 ppm/C", Tolerance_%=1%, Value2=0.063W, Value_Code=20R0, ValueDisplayed=20.0
R172 R258 R262 R266 R303 R341: library part CMP-0017779-3, "RES, 3.30, 1%, 0.25 W, AEC-Q200 Grade 0, 1206", Manufacturer=Panasonic, Power_W=250mW, Supplier Part Number 1=P3.3RCT-ND, TempCo="200 ppm/C", Tolerance_%=1%, Value2=0.25W, Value_Code=3R30, ValueDisplayed=3.30
R183 R312 R352: library part CMP-0023132-5, "RES, 47.5 k, 1%, 0.1 W, 0603", Manufacturer=Yageo, Power_W=100mW, Supplier Part Number 1=311-47.5KHRCT-ND, TempCo="100 ppm/C", Tolerance_%=1%, Value2=0.1W, Value_Code=47k5, ValueDisplayed=47.5k
R186 R535 R557: library part CMP-0026688-1, "RES, 249, 1%, 0.1 W, AEC-Q200 Grade 0, 0402", Manufacturer=Panasonic, Power_W=100mW, Supplier Part Number 1=P249LCT-ND, TempCo="100 ppm/C", Tolerance_%=1%, Value2=0.1W, Value_Code=249R, ValueDisplayed=249
R189: library part CMP-0020715-3, "RES, 390, 5%, 0.125 W, AEC-Q200 Grade 0, 0805", Manufacturer=Panasonic, Power_W=125mW, Supplier Part Number 1=P390ACT-ND, TempCo="200 ppm/C", Tolerance_%=5%, Value2=0.125W, Value_Code=390R, ValueDisplayed=390
R234 R244 R270 R276: library part CMP-0026786-1, "RES, 7.50 k, 0.1%, 0.063 W, AEC-Q200 Grade 0, 0402", Manufacturer=Panasonic, Power_W=63mW, Supplier Part Number 1=P7.5KDCCT-ND, TempCo="25 ppm/C", Tolerance_%=0.1%, Value2=0.063W, Value_Code=7k50, ValueDisplayed=7.50k
R254: library part CMP-0021282-3, "RES, 499, 1%, 0.125 W, AEC-Q200 Grade 0, 0805", Manufacturer=Vishay-Dale, Power_W=125mW, Supplier Part Number 1=541-499CCT-ND, TempCo="100 ppm/C", Tolerance_%=1%, Value2=0.125W, Value_Code=499R, ValueDisplayed=499
R318 R322 R323 R560 R561 R562 R568 R569 R570: library part CMP-0018640-3, "RES, 2.0 k, 5%, 0.25 W, AEC-Q200 Grade 0, 1206", Manufacturer=Vishay-Dale, Power_W=250mW, Supplier Part Number 1=541-2.0KECT-ND, TempCo="200 ppm/C", Tolerance_%=5%, Value2=0.25W, Value_Code=2k00, ValueDisplayed=2.0k
R374 R461: library part CMP-0026918-5, "RES, 3.3 k, 5%, 0.063 W, AEC-Q200 Grade 0, 0402", Manufacturer=Vishay-Dale, Power_W=63mW, Supplier Part Number 1=541-3.3KJCT-ND, TempCo="200 ppm/C", Tolerance_%=5%, Value2=0.063W, Value_Code=3k30, ValueDisplayed=3.3k
R380 R388 R412: library part CMP-0026827-3, "RES, 10, 5%, 0.063 W, AEC-Q200 Grade 0, 0402", Manufacturer=Vishay-Dale, Power_W=63mW, Supplier Part Number 1=541-10JCT-ND, TempCo="200 ppm/C", Tolerance_%=5%, Value2=0.063W, Value_Code=10R0, ValueDisplayed=10
R385 R386: library part CMP-0025431-3, "RES, 59.7, 0.5%, 0.1 W, 0603", Manufacturer="Yageo America", Power_W=100mW, TempCo="50 ppm/C", Tolerance_%=0.5%, Value2=0.1W, Value_Code=59R7, ValueDisplayed=59.7
RN1 RN2 RN3 RN4 RN5 RN6: library part CMP-0122946-1, "Automotive, 1700-V, Precision Resistive Divider", Manufacturer="Texas Instruments", Number Of Resistors=2, Operating Temperature Range="-40°C to +125°C", TempCo=1ppm/°C, Tolerance_%=0.05%
S1 S2 S3 S4 S5: library part CMP-0002139-2, "Switch, Slide, SPDT  100mA, SMT", CurrentRating_mA=100A, Manufacturer="Copal Electronics", Supplier Part Number 1=CAS120JCT-ND
TP1 TP3 TP63: library part CMP-0055147-2, "Test Point, Multipurpose, Red, TH", Color=Red, Manufacturer="Keystone Electronics", Supplier Part Number 1=36-5010-ND
TP2 TP4 TP10 TP12 TP13 TP64: library part CMP-0055148-2, "Test Point, Multipurpose, Black, TH", Color=Black, Manufacturer="Keystone Electronics", Supplier Part Number 1=36-5011-ND
TP5: library part CMP-0055137-2, "Test Point, Miniature, Red, TH", Color=Red, Manufacturer="Keystone Electronics", Supplier Part Number 1=36-5000-ND
TP6 TP16 TP18 TP19: library part CMP-0003825-1, "1mm Test Point, SMT", Manufacturer=Any
TP7 TP9 TP15 TP21 TP22 TP24 TP25 TP26 TP27 TP28 TP29 TP30 TP31 TP32 TP33 TP34 TP35 TP36 TP37 TP38 TP39 TP40 TP41 TP42 TP43 TP44 TP45 TP46 TP47 TP48 TP49 TP50 TP51 TP52 TP53 TP54 TP55 TP56 TP57 TP58 TP59 TP60 TP61 TP62 TP65 TP66 TP67: library part CMP-0003968-1, "Test Point, SMT", Manufacturer=Harwin, Supplier Part Number 1=952-2664-1-ND
TP8 TP11 TP14 TP17 TP20 TP23: library part CMP-0055138-2, "Test Point, Miniature, Black, TH", Color=Black, Manufacturer="Keystone Electronics", Supplier Part Number 1=36-5001-ND
U1: library part CMP-0088329-1, "2.7- 23V, 5.5 A, 28 mO Reverse Current Blocking eFuse with Input Reverse Polarity Protection", Manufacturer="Texas Instruments", Max Supply Voltage=23V, Min Supply Voltage=2.7V, Nominal Supply Current=0.5-6A, Operating Temperature Range="-40°C to +125°C", Output Voltage=42V, Threshold Voltage=1.2/1.1V
U2: library part CMP-0083940-3, "14 V Bidirectional Flat-Clamp Surge Protection Device, DRB0008A (VSON-8)", Alternate Manufacturer="Texas Instruments", Alternate PartNumber=TVS1401DRBT, Operating Temperature Range="-40 to 125 C"
U3: library part CMP-0034908-2, "3V to 16 V Input, 3-A Synchronous Step-Down Voltage Regulator Module, QFN-FCMOD7", Manufacturer="Texas Instruments", Max Supply Voltage=17V, Min Supply Voltage=3V, Nominal Supply Current=100-400uA, Operating Temperature Range="-40°C to +125°C", Output Voltage=0.6-10V, Switching Frequency=1.2MHz
U4: library part CMP-0066190-1, "Low-Drift, Low-Power, Dual-Output VREF and VREF/2 Voltage Reference, DDC0005A (SOT-23-T-5)", Alternate Manufacturer="Texas Instruments", Alternate PartNumber=REF2033AIDDCT
U5 U6 U7 U66: library part CMP-0013427-7, "500mA LDO, DRV0006A (WSON-6)", Alternate Manufacturer="Texas Instruments"
U8 U61: library part CMP-0121707-1, "Precision, Low-Offset-Voltage, Low-Noise, Low-Input-Bias-Current, Rail-to-Rail I/O, e-trim™ Operational Amplifiers", Digikey Part Number=296-OPA2392DRCT-ND, Input Bias Current=0.00000001uA, Input Offset Voltage=0.001mV, Manufacturer="Texas Instruments", Max Dual Supply Voltage=2.75V, Max Supply Voltage=5.5V, Min Dual Supply Voltage=850mV, Min Supply Voltage=1.7V, Mouser Part Number=595-OPA2392DR, Nominal Supply Current=1.22mA, Operating Temperature Range="-40°C to +125°C", Output Current Per Channel=65mA, Voltage Gain=132dB
U9: library part CMP-0121217-1, "Zero-Drift Amplifier 4 Circuit Rail-to-Rail 14-TSSOP", Digikey Part Number=296-OPA4388IPWRCT-ND, Input Bias Current=0.00003uA, Input Offset Voltage=0.00225mV, Manufacturer="Texas Instruments", Max Dual Supply Voltage=2.75V, Max Supply Voltage=5.5V, Min Dual Supply Voltage=1.25V, Min Supply Voltage=2.5V, Mouser Part Number=595-OPA4388IPWR, Nominal Supply Current=1.7-1.9mA, Operating Temperature Range="-40°C to +125°C", Output Current Per Channel=60mA, Voltage Gain=126dB
U10 U64 U65: library part CMP-0120116-1, "±24 V Low Capacitance Surge Diode for Industrial Networks in SOT-23 Package", Breakdown Voltage=25.5V, Clamping Voltage=35V, Digikey Part Number=296-TSM24CADBZRCT-ND, Manufacturer="Texas Instruments", Mouser Part Number=595-TSM24CADBZR, Operating Temperature Range="-55°C to +150°C", ValueDisplayed=14pF
U11: library part CMP-0033793-2, "Automotive 1.5-W, 12-V VIN / 12-VOUT, 15-V VIN / 15-V VOUT, HighDensity, > 5-kVRMS, Isolated DC/DC Module", Manufacturer="Texas Instruments", Max Supply Voltage=18V, Min Supply Voltage=9V, Nominal Supply Current=200-270mA, Operating Temperature Range="-40°C to +150°C", Output Voltage=10-18V, Switching Frequency=18MHz
U12: library part CMP-0095083-1, Manufacturer="Texas Instruments", Operating Temperature Range=to
U13: library part CMP-0088337-2, "Temperature Sensor Analog, Local -40°C ~ 150°C 10mV/°C SOT-23-3", Digikey Part Number=296-TMP235A2DBZRCT-ND, Manufacturer="Texas Instruments", Max Supply Voltage=5.5V, Min Supply Voltage=2.3V, Mouser Part Number=595-TMP235A2DBZR, Operating Supply Current=9uA, Operating Temperature Range="-40°C to +150°C"
U14 U15 U16: library part CMP-0121159-1, "High-precision, ±50-mV input, reinforced isolated modulator with integrated DC/DC converter 16-SOIC -40 to 125", Digikey Part Number=296-AMC3306M05DWERCT-ND, Manufacturer="Texas Instruments", Max Supply Voltage=5.5V, Min Supply Voltage=3V, Mouser Part Number=595-AMC3306M05DWER, Nominal Supply Current=26-28mA, Operating Temperature Range="-40°C to +125°C"
U17 U23 U30 U36 U43 U55 U56 U57 U58: library part CMP-0121477-1, "Automotive 1.5-W, 15-V VIN, 25-V VOUT, High-Density, > 5 kVRMS, Isolated DC/DC Module", Manufacturer="Texas Instruments", Max Supply Voltage=16.5V, Min Supply Voltage=13.5V, Nominal Supply Current=190mA, Operating Temperature Range="-40°C to +150°C", Output Voltage=15-25V, Switching Frequency=15MHz
U18 U37 U40 U44 U49 U59: library part CMP-0122725-1, "Automotive, Precision, ±1V Input Isolated Amplifiers With Single-Ended, Ratiometric Output", Input Bias Current=0.0035uA, Input Offset Voltage=0.4mV, Manufacturer="Texas Instruments", Max Supply Voltage=5.5V, Min Supply Voltage=3V, Operating Temperature Range="-40°C to +125°C", Output Current Per Channel=14mA
U19 U25 U26 U27 U38 U45: library part CMP-0080534-2, "Single Channel Isolated Gate Driver for SiC/IGBT with Advanced Protection and High-CMTI, DW0016B (SOIC-16)", Alternate Manufacturer="Texas Instruments", Alternate PartNumber=UCC21710QDWRQ1
U20 U32 U33 U34 U39 U46: library part CMP-0078841-1, "5-kVRMS Single-Channel Isolated Gate Drivers, DWV0008A (SOIC-8)", Alternate Manufacturer="Texas Instruments", Alternate PartNumber=UCC5350MCDWV
U21 U41 U47: library part CMP-0121162-1, "Precision 250kHz Hall-Effect Current Sensor With ±1.3kV Reinforced Isolation Working Voltage, Overcurrent Detection and Ambient Field Rejection", Coil Resistance=0.7mO, Current Sensitivity=50mV/A, Digikey Part Number=296-TMCS1123B2AQDVGRCT-ND, Manufacturer="Texas Instruments", Max Sensing Current=65A, Max Supply Voltage=5.5V, Min Supply Voltage=3V, Operating Supply Current=11mA, Operating Temperature Range="-40°C to +125°C"
U22 U42 U48: library part CMP-0122473-1, "Automotive ±1.5°C, 3-kVRMS Isolated Temperature Sensor With Analog Output With < 2 Seconds Response Time and 500VRMS Working Voltage", Manufacturer="Texas Instruments", Max Supply Voltage=5.5V, Min Supply Voltage=2.3V, Operating Supply Current=10uA, Operating Temperature Range="-40°C to +150°C"
U24 U63: library part CMP-0044881-2, Manufacturer="Texas Instruments", Operating Temperature Range=to
U28 U29: library part CMP-0080672-1, "Precision Reinforced Isolated Amplifier for Current Sensing, DWV0008A (SOIC-8)", Alternate Manufacturer="Texas Instruments", Alternate PartNumber=AMC1302DWV
U31: library part CMP-0074893-1, "100-mA, 30-V, Fixed-Output, Linear-Voltage Regulator, DBZ0003A (SOT-23-3)", Alternate Manufacturer="Texas Instruments", Alternate PartNumber=TLV76033DBZT
U35 U60 U62: library part CMP-0123146-1, "Ultra-Small, 1.5W, 5.0V, 5kVRMS Isolation, Industrial DC/DC Module", Manufacturer="Texas Instruments", Max Supply Voltage=5.5V, Min Supply Voltage=4.5V, Nominal Supply Current=7-545mA, Operating Temperature Range="-40°C to +125°C", Output Voltage=5/5.5V, Switching Frequency=76MHz
U50: library part CMP-0092023-2, "Reinforced 5-kVRMS Isolated CAN Transceiver with Integrated lowemissions DC-DC Converter", Manufacturer="Texas Instruments", Max Supply Voltage=5.5V, Min Supply Voltage=1.71V, Nominal Supply Current=0.3-124mA, Operating Temperature Range="-40°C to +105°C"
U51 U52 U53: library part CMP-0066280-1, "Quadruple Bus Buffer Gate with 3-State Outputs, PW0014A (TSSOP-14)", Alternate Manufacturer="Texas Instruments", Alternate PartNumber=SN74LVC126APW
U54: library part CMP-0094559-1, "Clock Clock Buffer IC 1:3 250 MHz 8-TSSOP", Digikey Part Number=296-LMK1C1103PWRCT-ND, Manufacturer="Texas Instruments", Max Supply Voltage=3.465V, Min Supply Voltage=1.71V, Mouser Part Number=595-LMK1C1103PWR, Nominal Supply Current=8-33mA, Operating Temperature Range="-40°C to +125°C"
ZZ1: library part CMP-0003616-3
ZZ2: library part CMP-0077236-1
ZZ3: library part CMP-0077237-1
ZZ4: library part CMP-0077238-1

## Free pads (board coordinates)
  rrect100% 2.29x4.06 hole 1.78 paste-1000 mask+0: 1(176.163,271.85) 1(176.165,180.882) 1(176.165,89.887) 1(193.853,299.48) 1(193.855,208.511) 1(193.855,117.516)
  round 0 hole 1 slot 8 at 90 deg unplated: 1(182.423,208.432) 1(182.423,299.237) 1(182.475,117.272) 1(187.629,181) 1(187.629,271.78) 1(187.681,89.84) 1(205.083,210.312) 1(205.13,300.812) 1(205.181,119.278) 1(210.839,179.121) 1(210.871,270.24) 1(210.936,88.138)

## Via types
v1: diameter 0.762, hole 0.356, Top Layer to Bottom Layer, tented both sides, 2905 vias
v2: diameter 0.61, hole 0.356, Top Layer to Bottom Layer, tented both sides, 1212 vias
v3: diameter 0.864, hole 0.406, Top Layer to Bottom Layer, tented both sides, 15 vias

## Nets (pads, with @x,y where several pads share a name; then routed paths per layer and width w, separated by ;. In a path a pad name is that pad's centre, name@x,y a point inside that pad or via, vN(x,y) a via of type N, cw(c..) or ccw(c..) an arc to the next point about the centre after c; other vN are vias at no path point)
1.65V: C20.1 C21.2 C100.1 C169.1 C223.2 C272.2 C310.1 C316.1 R176.2 R234.2 R270.2 R306.2 R345.2 R396.1 R411.2 TP5.1 U4.1 U9.3 | length 89.3
  Top Layer w0.203: R411.2@52.902,326.204 v2(52.902,327.028) ; v2(65.681,333.013) v2@65.701,332.993 ; R396.1@65.702,332.092 65.674,332.12 65.674,332.966 v2@65.701,332.993 ; v2@65.753,332.94 v2@65.701,332.993 ; R306.2@74.586,332.605 C100.1@75.51,332.605 v2(75.51,333.389) 74.845,334.054 66.763,334.054 v2@65.701,332.993 ; R345.2@74.6,320.753 C169.1@75.535,320.753 v2(76.302,320.753) ; U9.3@77.052,329.468 77.052,328.418 77.167,328.303 C310.1@79.511,328.303 v2(80.111,328.303) 80.111,326.002 82.66,323.453 v2(82.66,320.059) C272.2@83.347,320.059 R270.2@83.347,319.086 ; v2(77.362,319.955) C316.1@77.362,320.753 R176.2@78.251,320.753 ; v2(83.86,328.386) C223.2@84.625,328.386 R234.2@84.625,329.386
  Top Layer w0.305: TP5.1@97.291,319.7 C21.2@99.721,319.7 C20.1@99.721,321.5 99.716,321.505 U4.1@99.716,322.62
  Signal Layer 2 w0.203: v2(52.902,327.028) 52.902,328.303 53.275,328.676 54.598,328.676 55.118,329.196 58.674,329.196 58.674,329.319 62.367,333.013 v2(65.681,333.013) ; v2(75.51,333.389) 75.51,332.28 79.487,328.303 v2(80.111,328.303) ; v2@80.193,328.386 v2(83.86,328.386)
  Bottom Layer w0.203: v2(76.302,320.753) 77.362,320.753 ; v2(77.362,319.955) 77.362,320.753 ; v2(80.111,328.303) v2@80.193,328.386 ; v2@83.777,328.303 v2(83.86,328.386) ; TP5.1@97.291,319.7 83.019,319.7 v2(82.66,320.059) 81.966,320.753 77.362,320.753
3.3V_ISO_MID3: C237.1 C270.1 U29.1 U31.1 | length 5.7
  Top Layer w0.5: U29.1@121.85,11.82 121.85,11.112 122.604,10.357 C270.1@123.404,10.357 C237.1@124.604,10.357 126.362,10.357 U31.1@126.512,10.206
